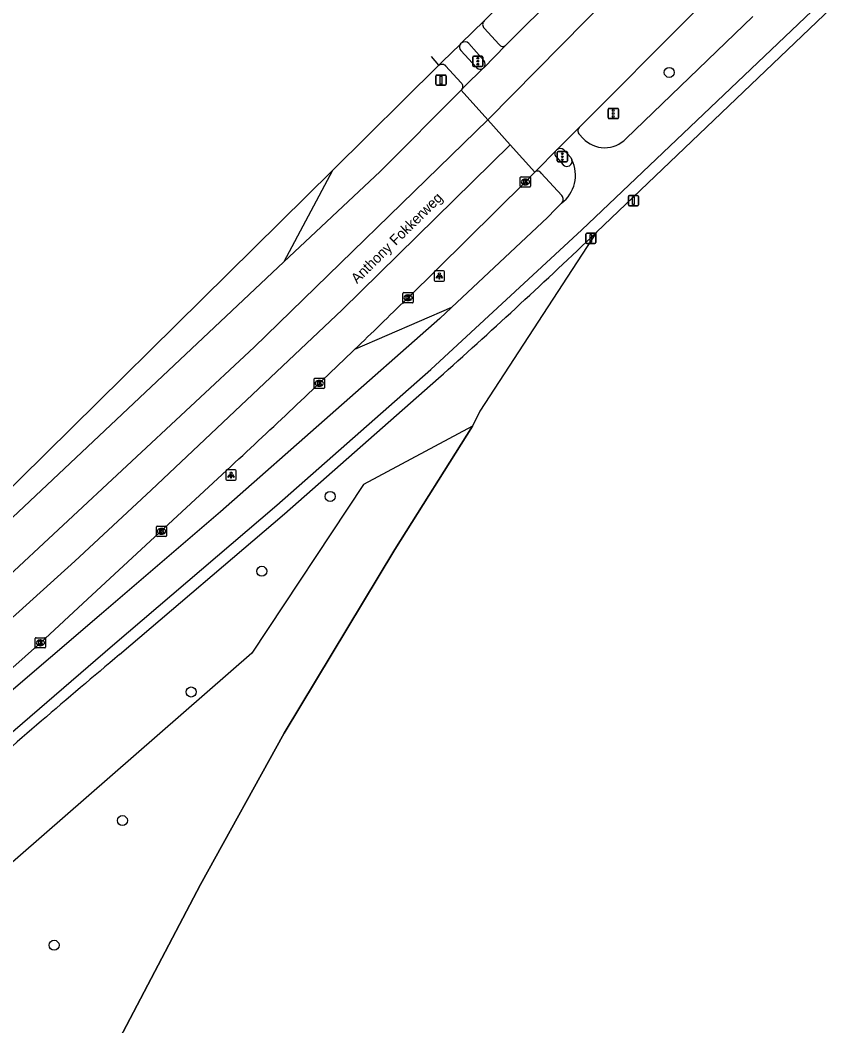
# Model space of a CAD drawing. Extents: x 158132 to 159658, y 385257 to 387209.
# Drawn here: x 158308.9 to 158387.6, y 386770.5 to 386868.4 of the extents above; entities that cross this region are included whole.
import ezdxf

# ---------------------------------------------------------------- set-up
doc = ezdxf.new("R2010")
doc.units = 0
for name, color, linetype in [('IMGEO_Berm_groen', 7, 'Continuous'), ('IMGEO_Boom', 7, 'Continuous'), ('IMGEO_Fietspad_gesloten', 7, 'Continuous'), ('IMGEO_Gemengd_bos', 7, 'Continuous'), ('IMGEO_Hek', 7, 'Continuous'), ('IMGEO_Kolk', 7, 'Continuous'), ('IMGEO_Lichtpunt', 7, 'Continuous'), ('IMGEO_Openbare_ruimte_label', 7, 'Continuous'), ('IMGEO_Rijbaan_regionaal_gesloten', 7, 'Continuous'), ('IMGEO_Verkeersbordpaal', 7, 'Continuous'), ('IMGEO_Verkeersregelinstallatiepaal', 7, 'Continuous'), ('IMGEO_Voetpad_open', 7, 'Continuous')]:
    doc.layers.add(name, color=color, linetype=linetype)

msp = doc.modelspace()

# ---------------------------------------------------------------- linework, layer by layer
at = {"layer": 'IMGEO_Berm_groen'}
for points in [[(158339.286, 386853.747), (158334.576, 386844.845)], [(158350.872, 386840.401), (158341.451, 386836.323)]]:
    msp.add_lwpolyline(points, dxfattribs=at)
at = {"layer": 'IMGEO_Boom'}
for centre in [(158372.058, 386863.272), (158339.074, 386822.04), (158332.417, 386814.755), (158325.554, 386803.019), (158318.862, 386790.512), (158312.215, 386778.384)]:
    msp.add_circle(centre, 0.489, dxfattribs=at)
at = {"layer": 'IMGEO_Fietspad_gesloten'}
for points in [[(158166.929, 386661.928), (158177.831, 386672.791), (158195.641, 386690.413), (158213.448, 386707.994), (158229.826, 386724.184), (158245.865, 386740.019), (158255.974, 386750), (158273.421, 386767.226), (158287.876, 386781.076), (158302.733, 386794.486), (158317.908, 386807.551), (158333.873, 386821.194), (158348.872, 386834.387), (158363.571, 386847.967), (158364.204, 386848.569), (158413.601, 386895.545), (158482.856, 386961.221)], [(158380.179, 386868.7), (158367.845, 386856.824)], [(158363.67, 386856.868), (158363.326, 386857.238)], [(158361.819, 386855.734), (158362.479, 386854.995), (158362.599, 386854.77)], [(158361.572, 386850.55), (158360.996, 386849.959), (158360.216, 386849.155), (158350.872, 386840.401)], [(158350.872, 386840.401), (158349.75, 386839.35), (158328.408, 386820.527), (158316.835, 386810.626), (158301.692, 386797.678), (158287.447, 386784.966), (158272.591, 386770.728), (158261.562, 386759.791), (158260.867, 386759.105), (158260.363, 386758.609)]]:
    msp.add_lwpolyline(points, dxfattribs=at)
for centre, radius, start, end in [((158363.63, 386857.581), 0.458, 135.69299, 228.45331), ((158365.778, 386858.814), 2.869, 222.70451, 316.08786), ((158361.469, 386855.353), 0.517, 47.47559, 134.45555), ((158359.534, 386853.281), 3.407, 306.72735, 25.91687)]:
    msp.add_arc(centre, radius, start, end, dxfattribs=at)
at = {"layer": 'IMGEO_Gemengd_bos'}
for points in [[(158364.996, 386847.739), (158353.626, 386830.335), (158352.936, 386828.869)], [(158352.936, 386828.869), (158342.321, 386823.189), (158331.457, 386806.798), (158295.112, 386775.077), (158281.865, 386761.228), (158272.172, 386742.51), (158258.528, 386724.959), (158189.373, 386636.002)], [(158352.936, 386828.869), (158345.353, 386816.876), (158334.612, 386799.008), (158326.456, 386784.3), (158312.425, 386757.541), (158308.916, 386750), (158297.101, 386724.536), (158284.405, 386694.182), (158276.641, 386675.619), (158267.448, 386652.131), (158257.822, 386629.602), (158248.717, 386612.814), (158244.396, 386604.736), (158234.281, 386586.759)]]:
    msp.add_lwpolyline(points, dxfattribs=at)
at = {"layer": 'IMGEO_Hek'}
for points in [[(158334.612, 386799.008), (158345.353, 386816.876), (158352.936, 386828.869)], [(158308.916, 386750), (158312.425, 386757.541), (158326.456, 386784.3), (158334.612, 386799.008)]]:
    msp.add_lwpolyline(points, dxfattribs=at)
at = {"layer": 'IMGEO_Kolk'}
for p, q in [((158357.564, 386852.194), (158357.564, 386853.046)), ((158357.639, 386853.12), (158358.491, 386853.12)), ((158358.052, 386852.9), (158358.077, 386852.9)), ((158358.565, 386853.046), (158358.565, 386852.194)), ((158358.491, 386852.12), (158357.639, 386852.12)), ((158358.075, 386852.34), (158358.05, 386852.34)), ((158346.152, 386840.928), (158346.152, 386841.78)), ((158346.227, 386841.854), (158347.079, 386841.854)), ((158346.64, 386841.634), (158346.665, 386841.634)), ((158347.153, 386841.78), (158347.153, 386840.928)), ((158347.079, 386840.854), (158346.227, 386840.854)), ((158346.663, 386841.074), (158346.638, 386841.074)), ((158337.513, 386832.606), (158337.513, 386833.458)), ((158337.588, 386833.532), (158338.44, 386833.532)), ((158338.001, 386833.312), (158338.026, 386833.312)), ((158338.514, 386833.458), (158338.514, 386832.606)), ((158338.44, 386832.532), (158337.588, 386832.532)), ((158338.024, 386832.752), (158337.999, 386832.752)), ((158322.167, 386818.213), (158322.167, 386819.065)), ((158322.242, 386819.139), (158323.094, 386819.139)), ((158322.655, 386818.919), (158322.68, 386818.919)), ((158323.168, 386819.065), (158323.168, 386818.213)), ((158323.094, 386818.139), (158322.242, 386818.139)), ((158322.678, 386818.359), (158322.653, 386818.359)), ((158310.383, 386807.372), (158310.383, 386808.224)), ((158310.458, 386808.298), (158311.31, 386808.298)), ((158310.871, 386808.078), (158310.896, 386808.078)), ((158311.384, 386808.224), (158311.384, 386807.372)), ((158311.31, 386807.298), (158310.458, 386807.298)), ((158310.894, 386807.518), (158310.869, 386807.518))]:
    msp.add_line(p, q, dxfattribs=at)
for points in [[(158357.564, 386852.194), (158357.564, 386853.046)], [(158357.639, 386853.12), (158358.491, 386853.12)], [(158358.565, 386853.046), (158358.565, 386852.194)], [(158358.491, 386852.12), (158357.639, 386852.12)], [(158357.885, 386852.82), (158358.008, 386852.82), (158358.008, 386852.669), (158358.138, 386852.82), (158358.302, 386852.82), (158358.156, 386852.669), (158358.309, 386852.42), (158358.157, 386852.42), (158358.072, 386852.584), (158358.008, 386852.517), (158358.008, 386852.42), (158357.885, 386852.42), (158357.885, 386852.82)], [(158346.152, 386840.928), (158346.152, 386841.78)], [(158346.227, 386841.854), (158347.079, 386841.854)], [(158346.473, 386841.554), (158346.596, 386841.554), (158346.596, 386841.403), (158346.726, 386841.554), (158346.89, 386841.554), (158346.744, 386841.403), (158346.897, 386841.154), (158346.745, 386841.154), (158346.66, 386841.318), (158346.596, 386841.251), (158346.596, 386841.154), (158346.473, 386841.154), (158346.473, 386841.554)], [(158347.153, 386841.78), (158347.153, 386840.928)], [(158347.079, 386840.854), (158346.227, 386840.854)], [(158337.513, 386832.606), (158337.513, 386833.458)], [(158337.588, 386833.532), (158338.44, 386833.532)], [(158338.514, 386833.458), (158338.514, 386832.606)], [(158338.44, 386832.532), (158337.588, 386832.532)], [(158337.834, 386833.232), (158337.957, 386833.232), (158337.957, 386833.081), (158338.087, 386833.232), (158338.251, 386833.232), (158338.105, 386833.081), (158338.258, 386832.832), (158338.106, 386832.832), (158338.021, 386832.996), (158337.957, 386832.929), (158337.957, 386832.832), (158337.834, 386832.832), (158337.834, 386833.232)], [(158322.167, 386818.213), (158322.167, 386819.065)], [(158322.242, 386819.139), (158323.094, 386819.139)], [(158322.488, 386818.839), (158322.611, 386818.839), (158322.611, 386818.688), (158322.741, 386818.839), (158322.905, 386818.839), (158322.759, 386818.688), (158322.912, 386818.439), (158322.76, 386818.439), (158322.675, 386818.603), (158322.611, 386818.536), (158322.611, 386818.439), (158322.488, 386818.439), (158322.488, 386818.839)], [(158323.168, 386819.065), (158323.168, 386818.213)], [(158323.094, 386818.139), (158322.242, 386818.139)], [(158310.383, 386807.372), (158310.383, 386808.224)], [(158310.458, 386808.298), (158311.31, 386808.298)], [(158310.704, 386807.998), (158310.827, 386807.998), (158310.827, 386807.847), (158310.957, 386807.998), (158311.121, 386807.998), (158310.975, 386807.847), (158311.128, 386807.598), (158310.976, 386807.598), (158310.891, 386807.762), (158310.827, 386807.695), (158310.827, 386807.598), (158310.704, 386807.598), (158310.704, 386807.998)], [(158311.384, 386808.224), (158311.384, 386807.372)], [(158311.31, 386807.298), (158310.458, 386807.298)]]:
    msp.add_lwpolyline(points, dxfattribs=at)
for centre, start, end in [((158357.641, 386853.044), 91.55205, 178.44795), ((158357.641, 386853.044), 91.55205, 178.44795), ((158358.489, 386853.044), 1.55205, 88.44795), ((158358.489, 386853.044), 1.55205, 88.44795), ((158357.641, 386852.196), 181.55205, 268.44795), ((158357.641, 386852.196), 181.55205, 268.44795), ((158358.489, 386852.196), 271.55205, 358.44795), ((158358.489, 386852.196), 271.55205, 358.44795), ((158346.229, 386841.778), 91.55205, 178.44795), ((158346.229, 386841.778), 91.55205, 178.44795), ((158347.077, 386841.778), 1.55205, 88.44795), ((158347.077, 386841.778), 1.55205, 88.44795), ((158346.229, 386840.93), 181.55205, 268.44795), ((158346.229, 386840.93), 181.55205, 268.44795), ((158347.077, 386840.93), 271.55205, 358.44795), ((158347.077, 386840.93), 271.55205, 358.44795), ((158337.59, 386833.456), 91.55205, 178.44795), ((158337.59, 386833.456), 91.55205, 178.44795), ((158338.438, 386833.456), 1.55205, 88.44795), ((158338.438, 386833.456), 1.55205, 88.44795), ((158337.59, 386832.608), 181.55205, 268.44795), ((158337.59, 386832.608), 181.55205, 268.44795), ((158338.438, 386832.608), 271.55205, 358.44795), ((158338.438, 386832.608), 271.55205, 358.44795), ((158322.244, 386819.063), 91.55205, 178.44795), ((158322.244, 386819.063), 91.55205, 178.44795), ((158323.092, 386819.063), 1.55205, 88.44795), ((158323.092, 386819.063), 1.55205, 88.44795), ((158322.244, 386818.215), 181.55205, 268.44795), ((158322.244, 386818.215), 181.55205, 268.44795), ((158323.092, 386818.215), 271.55205, 358.44795), ((158323.092, 386818.215), 271.55205, 358.44795), ((158310.46, 386808.222), 91.55205, 178.44795), ((158310.46, 386808.222), 91.55205, 178.44795), ((158311.308, 386808.222), 1.55205, 88.44795), ((158311.308, 386808.222), 1.55205, 88.44795), ((158310.46, 386807.374), 181.55205, 268.44795), ((158310.46, 386807.374), 181.55205, 268.44795), ((158311.308, 386807.374), 271.55205, 358.44795), ((158311.308, 386807.374), 271.55205, 358.44795)]:
    msp.add_arc(centre, 0.0765, start, end, dxfattribs=at)
for centre, major_axis, ratio, start_param, end_param in [((158358.051, 386852.62), (-0.387, 0.002), 0.722429, 4.712389, 7.853982), ((158358.076, 386852.62), (-0.39, 0.002), 0.717154, 1.570796, 4.712389), ((158346.639, 386841.354), (-0.387, 0.002), 0.722429, 4.712389, 7.853982), ((158346.664, 386841.354), (-0.39, 0.002), 0.717154, 1.570796, 4.712389), ((158338, 386833.032), (-0.387, 0.002), 0.722429, 4.712389, 7.853982), ((158338.025, 386833.032), (-0.39, 0.002), 0.717154, 1.570796, 4.712389), ((158322.654, 386818.639), (-0.387, 0.002), 0.722429, 4.712389, 7.853982), ((158322.679, 386818.639), (-0.39, 0.002), 0.717154, 1.570796, 4.712389), ((158310.87, 386807.798), (-0.387, 0.002), 0.722429, 4.712389, 7.853982), ((158310.895, 386807.798), (-0.39, 0.002), 0.717154, 1.570796, 4.712389)]:
    msp.add_ellipse(centre, major_axis=major_axis, ratio=ratio, start_param=start_param, end_param=end_param, dxfattribs=at)
at = {"layer": 'IMGEO_Lichtpunt'}
for p, q in [((158349.2, 386843.881), (158349.2, 386843.074)), ((158349.2, 386843.881), (158349.2, 386843.074)), ((158350.102, 386843.976), (158349.294, 386843.976)), ((158350.102, 386843.976), (158349.294, 386843.976)), ((158350.196, 386843.074), (158350.196, 386843.881)), ((158350.196, 386843.074), (158350.196, 386843.881)), ((158349.294, 386842.98), (158350.102, 386842.98)), ((158349.294, 386842.98), (158350.102, 386842.98)), ((158328.935, 386824.513), (158328.935, 386823.706)), ((158328.935, 386824.513), (158328.935, 386823.706)), ((158329.837, 386824.608), (158329.029, 386824.608)), ((158329.837, 386824.608), (158329.029, 386824.608)), ((158329.931, 386823.706), (158329.931, 386824.513)), ((158329.931, 386823.706), (158329.931, 386824.513)), ((158329.029, 386823.612), (158329.837, 386823.612)), ((158329.029, 386823.612), (158329.837, 386823.612))]:
    msp.add_line(p, q, dxfattribs=at)
for points in [[(158349.574, 386843.545), (158349.613, 386843.517), (158349.425, 386843.255), (158349.387, 386843.282), (158349.574, 386843.545)], [(158349.676, 386843.497), (158349.723, 386843.497), (158349.723, 386843.175), (158349.676, 386843.175), (158349.676, 386843.497)], [(158349.786, 386843.517), (158349.824, 386843.544), (158350.011, 386843.282), (158349.972, 386843.254), (158349.786, 386843.517)], [(158329.309, 386824.177), (158329.348, 386824.149), (158329.16, 386823.887), (158329.122, 386823.914), (158329.309, 386824.177)], [(158329.411, 386824.129), (158329.458, 386824.129), (158329.458, 386823.807), (158329.411, 386823.807), (158329.411, 386824.129)], [(158329.521, 386824.149), (158329.559, 386824.176), (158329.746, 386823.914), (158329.707, 386823.886), (158329.521, 386824.149)]]:
    msp.add_lwpolyline(points, dxfattribs=at)
for centre in [(158349.699, 386843.679), (158329.434, 386824.311)]:
    msp.add_circle(centre, 0.0994, dxfattribs=at)
for centre, start, end in [((158349.294, 386843.881), 90, 180), ((158349.294, 386843.881), 90, 180), ((158349.294, 386843.074), 180, 270), ((158349.294, 386843.074), 180, 270), ((158350.102, 386843.881), 0, 90), ((158350.102, 386843.881), 0, 90), ((158350.102, 386843.074), 270, 0), ((158350.102, 386843.074), 270, 360), ((158329.029, 386824.513), 90, 180), ((158329.029, 386824.513), 90, 180), ((158329.837, 386824.513), 0, 90), ((158329.837, 386824.513), 0, 90), ((158329.029, 386823.706), 180, 270), ((158329.029, 386823.706), 180, 270), ((158329.837, 386823.706), 270, 0), ((158329.837, 386823.706), 270, 360)]:
    msp.add_arc(centre, 0.0946, start, end, dxfattribs=at)
at = {"layer": 'IMGEO_Rijbaan_regionaal_gesloten'}
for points in [[(158354.405, 386858.667), (158380.582, 386885.204)], [(158363.302, 386857.901), (158374.297, 386868.932), (158382.963, 386877.591), (158384.415, 386878.977), (158385.753, 386880.108), (158386.606, 386880.879)], [(158354.052, 386868.284), (158359.141, 386873.301)], [(158360.54, 386873.315), (158361.045, 386872.801), (158361.335, 386872.506), (158361.359, 386872.481), (158361.417, 386872.411), (158361.468, 386872.337), (158361.513, 386872.258), (158361.551, 386872.176), (158361.581, 386872.09), (158361.603, 386872.002), (158361.617, 386871.913), (158361.624, 386871.823), (158361.622, 386871.732), (158361.612, 386871.642), (158361.594, 386871.553), (158361.568, 386871.466), (158361.535, 386871.382), (158361.494, 386871.301), (158361.446, 386871.224), (158361.392, 386871.152), (158361.331, 386871.085), (158356.141, 386865.903)], [(158351.83, 386866.106), (158354.052, 386868.284)], [(158349.653, 386863.98), (158349.973, 386864.292), (158351.754, 386866.032)], [(158351.754, 386866.032), (158351.83, 386866.106)], [(158356.141, 386865.903), (158354.02, 386863.726)], [(158349.653, 386863.98), (158348.917, 386864.83)], [(158339.286, 386853.747), (158349.635, 386863.962)], [(158349.635, 386863.962), (158349.653, 386863.98)], [(158353.967, 386863.681), (158352.153, 386861.887), (158351.814, 386861.552)], [(158354.02, 386863.726), (158353.967, 386863.681)], [(158334.576, 386844.845), (158343.924, 386853.635), (158351.814, 386861.552)], [(158351.814, 386861.552), (158354.405, 386858.667)], [(158354.405, 386858.667), (158331.688, 386836.549), (158306.861, 386813.476), (158285.425, 386794.18), (158278.775, 386788.64)], [(158356.589, 386856.236), (158354.405, 386858.667)], [(158363.302, 386857.901), (158361.107, 386855.722)], [(158356.589, 386856.236), (158340.238, 386840.168), (158321.676, 386822.629), (158314.244, 386815.736), (158294.951, 386798.316), (158279.955, 386784.775), (158256.904, 386762.898), (158241.824, 386747.948), (158228.64, 386734.94), (158222.931, 386729.307), (158189.476, 386696.3), (158157.589, 386664.888), (158137.101, 386644.381)], [(158358.97, 386853.584), (158356.589, 386856.236)], [(158358.97, 386853.584), (158359.261, 386853.875), (158361, 386855.615)], [(158361, 386855.615), (158361.107, 386855.722)], [(158253.35, 386768.8), (158301.247, 386816.201), (158339.286, 386853.747)], [(158346.495, 386841.217), (158346.652, 386841.355), (158358.064, 386852.621), (158358.97, 386853.584)], [(158278.775, 386788.64), (158300.93, 386813.144), (158303.073, 386815.22), (158334.576, 386844.845)], [(158259.078, 386760.052), (158259.554, 386760.522), (158259.571, 386760.539), (158260.165, 386761.127), (158266.109, 386766.913), (158268.115, 386768.857), (158280.397, 386780.306), (158286.465, 386785.885), (158302.832, 386800.638), (158310.884, 386807.798), (158315.481, 386812.035), (158329.433, 386824.975)]]:
    msp.add_lwpolyline(points, dxfattribs=at)
for centre, radius, start, end in [((157735.88, 387465.501), 873.259, 313.904707, 314.365827), ((157743.706, 387457.322), 861.939, 312.808166, 313.90692)]:
    msp.add_arc(centre, radius, start, end, dxfattribs=at)
at = {"layer": 'IMGEO_Verkeersbordpaal'}
for p, q in [((158349.358, 386862.118), (158349.358, 386862.918)), ((158349.358, 386862.918), (158349.358, 386862.118)), ((158349.458, 386863.018), (158350.248, 386863.018)), ((158350.248, 386863.018), (158349.458, 386863.018)), ((158350.348, 386862.918), (158350.348, 386862.118)), ((158350.348, 386862.118), (158350.348, 386862.918)), ((158350.248, 386862.018), (158349.458, 386862.018)), ((158349.458, 386862.018), (158350.248, 386862.018)), ((158368.081, 386850.404), (158368.081, 386851.204)), ((158368.081, 386851.204), (158368.081, 386850.404)), ((158368.181, 386851.304), (158368.971, 386851.304)), ((158368.971, 386851.304), (158368.181, 386851.304)), ((158369.071, 386851.204), (158369.071, 386850.404)), ((158369.071, 386850.404), (158369.071, 386851.204)), ((158368.971, 386850.304), (158368.181, 386850.304)), ((158368.181, 386850.304), (158368.971, 386850.304)), ((158363.938, 386846.734), (158363.938, 386847.534)), ((158363.938, 386847.534), (158363.938, 386846.734)), ((158364.038, 386847.634), (158364.828, 386847.634)), ((158364.828, 386847.634), (158364.038, 386847.634)), ((158364.928, 386847.534), (158364.928, 386846.734)), ((158364.928, 386846.734), (158364.928, 386847.534)), ((158364.828, 386846.634), (158364.038, 386846.634)), ((158364.038, 386846.634), (158364.828, 386846.634))]:
    msp.add_line(p, q, dxfattribs=at)
for points in [[(158349.778, 386862.893), (158349.928, 386862.893), (158349.928, 386862.143), (158349.778, 386862.143), (158349.778, 386862.893)], [(158368.501, 386851.179), (158368.651, 386851.179), (158368.651, 386850.429), (158368.501, 386850.429), (158368.501, 386851.179)], [(158364.358, 386847.509), (158364.508, 386847.509), (158364.508, 386846.759), (158364.358, 386846.759), (158364.358, 386847.509)]]:
    msp.add_lwpolyline(points, dxfattribs=at)
for centre, start, end in [((158349.458, 386862.918), 90, 180), ((158349.458, 386862.918), 90, 180), ((158350.248, 386862.918), 0, 90), ((158350.248, 386862.918), 360, 90), ((158349.458, 386862.118), 180, 270), ((158349.458, 386862.118), 180, 270), ((158350.248, 386862.118), 270, 0), ((158350.248, 386862.118), 270, 0), ((158368.181, 386851.204), 90, 180), ((158368.181, 386851.204), 90, 180), ((158368.971, 386851.204), 0, 90), ((158368.971, 386851.204), 360, 90), ((158368.181, 386850.404), 180, 270), ((158368.181, 386850.404), 180, 270), ((158368.971, 386850.404), 270, 0), ((158368.971, 386850.404), 270, 0), ((158364.038, 386847.534), 90, 180), ((158364.038, 386847.534), 90, 180), ((158364.828, 386847.534), 0, 90), ((158364.828, 386847.534), 360, 90), ((158364.038, 386846.734), 180, 270), ((158364.038, 386846.734), 180, 270), ((158364.828, 386846.734), 270, 0), ((158364.828, 386846.734), 270, 0)]:
    msp.add_arc(centre, 0.1, start, end, dxfattribs=at)
at = {"layer": 'IMGEO_Verkeersregelinstallatiepaal'}
for p, q in [((158352.937, 386863.958), (158352.937, 386864.758)), ((158352.937, 386864.758), (158352.937, 386863.958)), ((158353.037, 386864.858), (158353.827, 386864.858)), ((158353.827, 386864.858), (158353.037, 386864.858)), ((158353.927, 386864.758), (158353.927, 386863.958)), ((158353.927, 386863.958), (158353.927, 386864.758)), ((158353.827, 386863.858), (158353.037, 386863.858)), ((158353.037, 386863.858), (158353.827, 386863.858)), ((158366.218, 386859.775), (158367.008, 386859.775)), ((158367.008, 386859.775), (158366.218, 386859.775)), ((158366.118, 386858.875), (158366.118, 386859.675)), ((158366.118, 386859.675), (158366.118, 386858.875)), ((158367.008, 386858.775), (158366.218, 386858.775)), ((158366.218, 386858.775), (158367.008, 386858.775)), ((158367.108, 386859.675), (158367.108, 386858.875)), ((158367.108, 386858.875), (158367.108, 386859.675)), ((158361.161, 386854.669), (158361.161, 386855.469)), ((158361.161, 386855.469), (158361.161, 386854.669)), ((158361.261, 386855.569), (158362.051, 386855.569)), ((158362.051, 386855.569), (158361.261, 386855.569)), ((158362.151, 386855.469), (158362.151, 386854.669)), ((158362.151, 386854.669), (158362.151, 386855.469)), ((158362.051, 386854.569), (158361.261, 386854.569)), ((158361.261, 386854.569), (158362.051, 386854.569))]:
    msp.add_line(p, q, dxfattribs=at)
for centre in [(158353.432, 386864.648), (158353.432, 386864.358), (158353.432, 386864.068), (158366.613, 386859.565), (158366.613, 386859.275), (158366.613, 386858.985), (158361.656, 386855.359), (158361.656, 386855.069), (158361.656, 386854.779)]:
    msp.add_circle(centre, 0.085, dxfattribs=at)
for centre, start, end in [((158353.037, 386864.758), 90, 180), ((158353.037, 386864.758), 90, 180), ((158353.827, 386864.758), 0, 90), ((158353.827, 386864.758), 360, 90), ((158353.037, 386863.958), 180, 270), ((158353.037, 386863.958), 180, 270), ((158353.827, 386863.958), 270, 0), ((158353.827, 386863.958), 270, 0), ((158366.218, 386859.675), 90, 180), ((158366.218, 386859.675), 90, 180), ((158367.008, 386859.675), 0, 90), ((158367.008, 386859.675), 360, 90), ((158366.218, 386858.875), 180, 270), ((158366.218, 386858.875), 180, 270), ((158367.008, 386858.875), 270, 0), ((158367.008, 386858.875), 270, 0), ((158361.261, 386855.469), 90, 180), ((158361.261, 386855.469), 90, 180), ((158362.051, 386855.469), 0, 90), ((158362.051, 386855.469), 360, 90), ((158361.261, 386854.669), 180, 270), ((158361.261, 386854.669), 180, 270), ((158362.051, 386854.669), 270, 0), ((158362.051, 386854.669), 270, 0)]:
    msp.add_arc(centre, 0.1, start, end, dxfattribs=at)
at = {"layer": 'IMGEO_Voetpad_open'}
for points in [[(158484.899, 386961.632), (158414.28, 386894.81), (158364.996, 386847.739)], [(158354.062, 386867.559), (158355.511, 386865.972)], [(158354.043, 386864.41), (158352.56, 386866.083)], [(158353.325, 386863.735), (158351.799, 386865.406)], [(158349.635, 386863.962), (158349.667, 386863.988), (158349.701, 386864.012), (158349.738, 386864.033), (158349.776, 386864.05), (158349.815, 386864.064), (158349.855, 386864.074), (158349.897, 386864.081), (158349.938, 386864.084), (158349.98, 386864.083), (158350.022, 386864.078), (158350.063, 386864.07), (158350.103, 386864.058), (158350.142, 386864.043), (158350.179, 386864.024), (158350.214, 386864.002), (158350.248, 386863.977), (158350.279, 386863.949), (158350.307, 386863.918), (158351.833, 386862.247), (158351.854, 386862.221), (158351.881, 386862.184), (158351.903, 386862.144), (158351.922, 386862.102), (158351.938, 386862.059), (158351.949, 386862.015), (158351.957, 386861.97), (158351.96, 386861.925), (158351.959, 386861.879), (158351.954, 386861.834), (158351.946, 386861.789), (158351.933, 386861.745), (158351.916, 386861.702), (158351.896, 386861.661), (158351.872, 386861.623), (158351.844, 386861.586), (158351.814, 386861.552)], [(158361.121, 386855.003), (158361.735, 386854.279)], [(158361.609, 386851.287), (158359.606, 386853.487)], [(158364.464, 386847.231), (158364.996, 386847.739)], [(158318.594, 386806.662), (158334.63, 386820.357), (158349.615, 386833.543)]]:
    msp.add_lwpolyline(points, dxfattribs=at)
for centre, radius, start, end in [((158354.407, 386867.926), 0.504, 134.75456, 226.82591), ((158352.111, 386865.743), 0.46, 141.04358, 227.17969), ((158352.183, 386865.709), 0.531, 44.72437, 131.66641), ((158355.857, 386866.223), 0.428, 215.9858, 311.51352), ((158353.677, 386864.073), 0.488, 223.8891, 306.49499), ((158353.652, 386864.081), 0.511, 316.0144, 40.13382), ((158361.354, 386855.367), 0.432, 144.97822, 237.38948), ((158362.098, 386854.647), 0.516, 225.41302, 13.805), ((158359.243, 386853.243), 0.437, 33.96859, 128.68804), ((158361.228, 386850.937), 0.517, 311.63592, 42.616), ((157967.935, 387262.495), 574.177, 311.662584, 313.67794), ((158836.43, 386188.944), 806.058, 129.973273, 131.391309)]:
    msp.add_arc(centre, radius, start, end, dxfattribs=at)

# ---------------------------------------------------------------- texts
at = {"layer": 'IMGEO_Openbare_ruimte_label'}
msp.add_text('Anthony Fokkerweg', height=1, rotation=44.63558, dxfattribs=at).set_placement((158341.69, 386842.674))

doc.saveas('drawing.dxf')
